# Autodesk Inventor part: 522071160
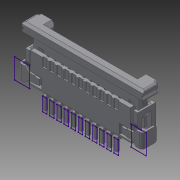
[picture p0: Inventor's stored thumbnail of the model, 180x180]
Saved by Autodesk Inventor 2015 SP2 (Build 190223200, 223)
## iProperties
Created: 2012-08
Part Number: 522071160
Material: Allgemein
Document SubType Name: Modeling
Designer: rYan
Categories: <MemberInstance><Categories><Category DisplayName="" Mnemonic="CABLEANDHARNESS" InternalName="e4a7e005-5e42-4d16-b293-125e7f0d0512"><Category DisplayName="" Mne
Density: 1 g/cm^3
Mass: 0.182449 g
Surface Area: 8.62074 cm^2
Volume: 0.182449 cm^3
Appearance: Vorgabe
Übersetzungsnorm: STEP AP203
Dateiname: 522071160
Vorprozessor: PRO/ENGINEER BY PARAMETRIC TECHNOLOGY CORPORATION, 2003451
Postprozessor: Build: 138, Release: 2013 RTM - Date: Thu 03/01/2012
Gesendete Einheiten: Millimeter
Unbestimmtheit: 0.002074742300838
Author: rYan
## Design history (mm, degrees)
node "5220711601"
  sketch "3D-Skizze1"
workpoint "Arbeitspunkt1"
node "1"
node "2"
node "3"
node "4"
node "5"
node "6"
node "7"
node "8"
node "9"
node "10"
node "11"
node "522071160"
node "522071160_1"
node "522071160_2"
node "Basis1"
node "Basis2"
node "Basis3"
